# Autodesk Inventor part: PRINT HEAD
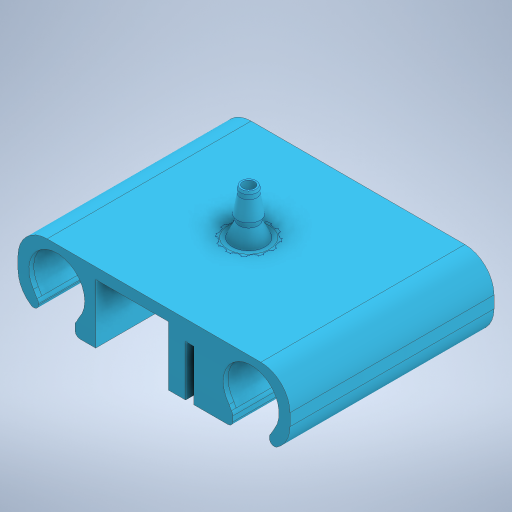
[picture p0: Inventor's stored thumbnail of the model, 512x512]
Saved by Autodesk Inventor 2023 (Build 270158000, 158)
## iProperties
Created: 2025-07
Part Number: PRINT HEAD
Material: Generic
Document SubType Name: Modeling
Designer: erjon
Density: 1 g/cm^3
Appearance: Default
Author: erjon
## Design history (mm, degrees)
feature "Base1"
feature "Base2"
body "Solid1"
body "Solid2"
